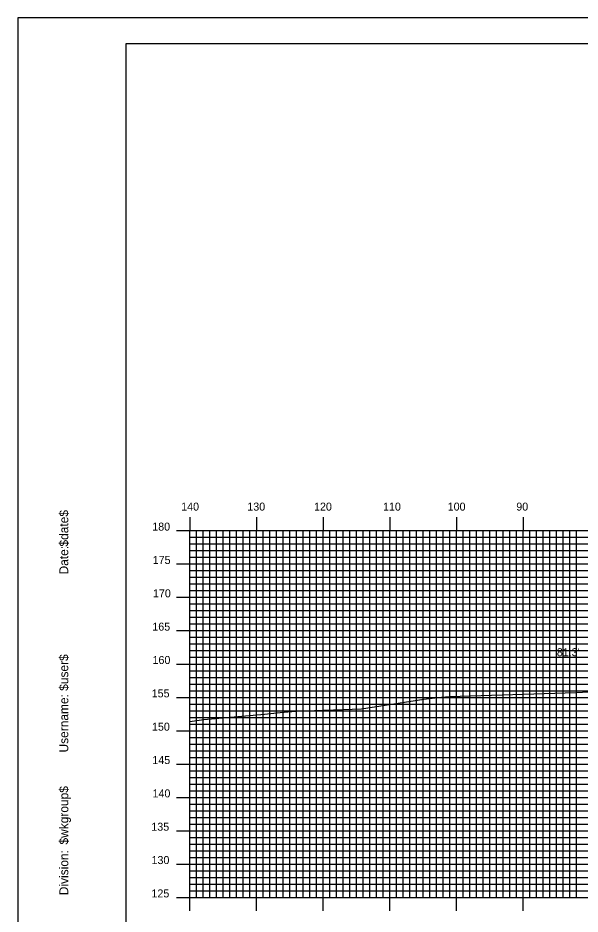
# Model space of a CAD drawing. Extents: x 1783434 to 1783777, y 442591 to 442811.
# Drawn here: x 1783434.2 to 1783518.5, y 442676.2 to 442810.5 of the extents above; entities that cross this region are included whole.
import ezdxf

# ---------------------------------------------------------------- set-up
doc = ezdxf.new("R2010")
doc.units = 0
for name, color, linetype in [('BORDER', 7, 'Continuous'), ('D_Text_Standard', 7, 'Continuous'), ('H_V ANNOTATION', 7, 'Continuous'), ('MAJOR', 7, 'Continuous'), ('MINOR', 7, 'Continuous'), ('PLOT BOUNDARY', 7, 'Continuous'), ('S_Roadway_Centerline', 7, 'Continuous')]:
    doc.layers.add(name, color=color, linetype=linetype)

msp = doc.modelspace()

# ---------------------------------------------------------------- linework, layer by layer
at = {"layer": 'BORDER'}
msp.add_lwpolyline([(1783450.37, 442596.67), (1783770.37, 442596.67), (1783770.37, 442806.67), (1783450.37, 442806.67)], close=True, dxfattribs=at)
at = {"layer": 'MAJOR'}
for p, q in [((1783459.97, 442735.67), (1783459.97, 442733.67)), ((1783469.97, 442735.67), (1783469.97, 442733.67)), ((1783479.97, 442735.67), (1783479.97, 442733.67)), ((1783489.97, 442735.67), (1783489.97, 442733.67)), ((1783499.97, 442735.67), (1783499.97, 442733.67)), ((1783509.97, 442735.67), (1783509.97, 442733.67)), ((1783457.97, 442733.67), (1783459.97, 442733.67)), ((1783459.97, 442733.67), (1783739.97, 442733.67)), ((1783459.97, 442678.67), (1783459.97, 442733.67)), ((1783459.97, 442678.67), (1783459.97, 442733.67)), ((1783459.97, 442733.67), (1783739.97, 442733.67)), ((1783469.97, 442678.67), (1783469.97, 442733.67)), ((1783479.97, 442678.67), (1783479.97, 442733.67)), ((1783489.97, 442678.67), (1783489.97, 442733.67)), ((1783499.97, 442678.67), (1783499.97, 442733.67)), ((1783509.97, 442678.67), (1783509.97, 442733.67)), ((1783457.97, 442728.67), (1783459.97, 442728.67)), ((1783459.97, 442728.67), (1783739.97, 442728.67)), ((1783457.97, 442723.67), (1783459.97, 442723.67)), ((1783459.97, 442723.67), (1783739.97, 442723.67)), ((1783457.97, 442718.67), (1783459.97, 442718.67)), ((1783459.97, 442718.67), (1783739.97, 442718.67)), ((1783457.97, 442713.67), (1783459.97, 442713.67)), ((1783459.97, 442713.67), (1783739.97, 442713.67)), ((1783457.97, 442708.67), (1783459.97, 442708.67)), ((1783459.97, 442708.67), (1783739.97, 442708.67)), ((1783457.97, 442703.67), (1783459.97, 442703.67)), ((1783459.97, 442703.67), (1783739.97, 442703.67)), ((1783457.97, 442698.67), (1783459.97, 442698.67)), ((1783459.97, 442698.67), (1783739.97, 442698.67)), ((1783457.97, 442693.67), (1783459.97, 442693.67)), ((1783459.97, 442693.67), (1783739.97, 442693.67)), ((1783457.97, 442688.67), (1783459.97, 442688.67)), ((1783459.97, 442688.67), (1783739.97, 442688.67)), ((1783457.97, 442683.67), (1783459.97, 442683.67)), ((1783459.97, 442683.67), (1783739.97, 442683.67)), ((1783457.97, 442678.67), (1783459.97, 442678.67)), ((1783459.97, 442678.67), (1783739.97, 442678.67)), ((1783459.97, 442678.67), (1783739.97, 442678.67)), ((1783459.97, 442676.66), (1783459.97, 442678.67)), ((1783469.97, 442676.66), (1783469.97, 442678.67)), ((1783479.97, 442676.66), (1783479.97, 442678.67)), ((1783489.97, 442676.66), (1783489.97, 442678.67)), ((1783499.97, 442676.66), (1783499.97, 442678.67)), ((1783509.97, 442676.66), (1783509.97, 442678.67))]:
    msp.add_line(p, q, dxfattribs=at)
at = {"layer": 'MINOR'}
for p, q in [((1783459.97, 442732.67), (1783739.97, 442732.67)), ((1783459.97, 442732.67), (1783461.98, 442732.67)), ((1783460.97, 442678.67), (1783460.97, 442733.67)), ((1783461.97, 442678.67), (1783461.97, 442733.67)), ((1783462.97, 442678.67), (1783462.97, 442733.67)), ((1783463.97, 442678.67), (1783463.97, 442733.67)), ((1783464.97, 442678.67), (1783464.97, 442733.67)), ((1783465.97, 442678.67), (1783465.97, 442733.67)), ((1783466.97, 442678.67), (1783466.97, 442733.67)), ((1783467.97, 442678.67), (1783467.97, 442733.67)), ((1783468.97, 442678.67), (1783468.97, 442733.67)), ((1783470.97, 442678.67), (1783470.97, 442733.67)), ((1783471.97, 442678.67), (1783471.97, 442733.67)), ((1783472.97, 442678.67), (1783472.97, 442733.67)), ((1783473.97, 442678.67), (1783473.97, 442733.67)), ((1783474.97, 442678.67), (1783474.97, 442733.67)), ((1783475.97, 442678.67), (1783475.97, 442733.67)), ((1783476.97, 442678.67), (1783476.97, 442733.67)), ((1783477.97, 442678.67), (1783477.97, 442733.67)), ((1783478.97, 442678.67), (1783478.97, 442733.67)), ((1783480.97, 442678.67), (1783480.97, 442733.67)), ((1783481.97, 442678.67), (1783481.97, 442733.67)), ((1783482.97, 442678.67), (1783482.97, 442733.67)), ((1783483.97, 442678.67), (1783483.97, 442733.67)), ((1783484.97, 442678.67), (1783484.97, 442733.67)), ((1783485.97, 442678.67), (1783485.97, 442733.67)), ((1783486.97, 442678.67), (1783486.97, 442733.67)), ((1783487.97, 442678.67), (1783487.97, 442733.67)), ((1783488.97, 442678.67), (1783488.97, 442733.67)), ((1783490.97, 442678.67), (1783490.97, 442733.67)), ((1783491.97, 442678.67), (1783491.97, 442733.67)), ((1783492.97, 442678.67), (1783492.97, 442733.67)), ((1783493.97, 442678.67), (1783493.97, 442733.67)), ((1783494.97, 442678.67), (1783494.97, 442733.67)), ((1783495.97, 442678.67), (1783495.97, 442733.67)), ((1783496.97, 442678.67), (1783496.97, 442733.67)), ((1783497.97, 442678.67), (1783497.97, 442733.67)), ((1783498.97, 442678.67), (1783498.97, 442733.67)), ((1783500.97, 442678.67), (1783500.97, 442733.67)), ((1783501.97, 442678.67), (1783501.97, 442733.67)), ((1783502.97, 442678.67), (1783502.97, 442733.67)), ((1783503.97, 442678.67), (1783503.97, 442733.67)), ((1783504.97, 442678.67), (1783504.97, 442733.67)), ((1783505.97, 442678.67), (1783505.97, 442733.67)), ((1783506.97, 442678.67), (1783506.97, 442733.67)), ((1783507.97, 442678.67), (1783507.97, 442733.67)), ((1783508.97, 442678.67), (1783508.97, 442733.67)), ((1783510.97, 442678.67), (1783510.97, 442733.67)), ((1783511.97, 442678.67), (1783511.97, 442733.67)), ((1783512.97, 442678.67), (1783512.97, 442733.67)), ((1783513.97, 442678.67), (1783513.97, 442733.67)), ((1783514.97, 442678.67), (1783514.97, 442733.67)), ((1783515.97, 442678.67), (1783515.97, 442733.67)), ((1783516.97, 442678.67), (1783516.97, 442733.67)), ((1783517.97, 442678.67), (1783517.97, 442733.67)), ((1783459.97, 442731.67), (1783739.97, 442731.67)), ((1783459.97, 442731.67), (1783461.98, 442731.67)), ((1783459.97, 442730.67), (1783739.97, 442730.67)), ((1783459.97, 442730.67), (1783461.98, 442730.67)), ((1783459.97, 442729.67), (1783739.97, 442729.67)), ((1783459.97, 442729.67), (1783461.98, 442729.67)), ((1783459.97, 442727.67), (1783739.97, 442727.67)), ((1783459.97, 442727.67), (1783461.98, 442727.67)), ((1783459.97, 442726.67), (1783739.97, 442726.67)), ((1783459.97, 442726.67), (1783461.98, 442726.67)), ((1783459.97, 442725.67), (1783739.97, 442725.67)), ((1783459.97, 442725.67), (1783461.98, 442725.67)), ((1783459.97, 442724.67), (1783739.97, 442724.67)), ((1783459.97, 442724.67), (1783461.98, 442724.67)), ((1783459.97, 442722.67), (1783739.97, 442722.67)), ((1783459.97, 442722.67), (1783461.98, 442722.67)), ((1783459.97, 442721.67), (1783739.97, 442721.67)), ((1783459.97, 442721.67), (1783461.98, 442721.67)), ((1783459.97, 442720.67), (1783739.97, 442720.67)), ((1783459.97, 442720.67), (1783461.98, 442720.67)), ((1783459.97, 442719.67), (1783739.97, 442719.67)), ((1783459.97, 442719.67), (1783461.98, 442719.67)), ((1783459.97, 442717.67), (1783739.97, 442717.67)), ((1783459.97, 442717.67), (1783461.98, 442717.67)), ((1783459.97, 442716.67), (1783739.97, 442716.67)), ((1783459.97, 442716.67), (1783461.98, 442716.67)), ((1783459.97, 442715.67), (1783739.97, 442715.67)), ((1783459.97, 442715.67), (1783461.98, 442715.67)), ((1783459.97, 442714.67), (1783739.97, 442714.67)), ((1783459.97, 442714.67), (1783461.98, 442714.67)), ((1783459.97, 442712.67), (1783739.97, 442712.67)), ((1783459.97, 442712.67), (1783461.98, 442712.67)), ((1783459.97, 442711.67), (1783739.97, 442711.67)), ((1783459.97, 442711.67), (1783461.98, 442711.67)), ((1783459.97, 442710.67), (1783739.97, 442710.67)), ((1783459.97, 442710.67), (1783461.98, 442710.67)), ((1783459.97, 442709.67), (1783739.97, 442709.67)), ((1783459.97, 442709.67), (1783461.98, 442709.67)), ((1783459.97, 442707.67), (1783739.97, 442707.67)), ((1783459.97, 442707.67), (1783461.98, 442707.67)), ((1783459.97, 442706.67), (1783739.97, 442706.67)), ((1783459.97, 442706.67), (1783461.98, 442706.67)), ((1783459.97, 442705.67), (1783739.97, 442705.67)), ((1783459.97, 442705.67), (1783461.98, 442705.67)), ((1783459.97, 442704.67), (1783739.97, 442704.67)), ((1783459.97, 442704.67), (1783461.98, 442704.67)), ((1783459.97, 442702.67), (1783739.97, 442702.67)), ((1783459.97, 442702.67), (1783461.98, 442702.67)), ((1783459.97, 442701.67), (1783739.97, 442701.67)), ((1783459.97, 442701.67), (1783461.98, 442701.67)), ((1783459.97, 442700.67), (1783739.97, 442700.67)), ((1783459.97, 442700.67), (1783461.98, 442700.67)), ((1783459.97, 442699.67), (1783739.97, 442699.67)), ((1783459.97, 442699.67), (1783461.98, 442699.67)), ((1783459.97, 442697.67), (1783739.97, 442697.67)), ((1783459.97, 442697.67), (1783461.98, 442697.67)), ((1783459.97, 442696.67), (1783739.97, 442696.67)), ((1783459.97, 442696.67), (1783461.98, 442696.67)), ((1783459.97, 442695.67), (1783739.97, 442695.67)), ((1783459.97, 442695.67), (1783461.98, 442695.67)), ((1783459.97, 442694.67), (1783739.97, 442694.67)), ((1783459.97, 442694.67), (1783461.98, 442694.67)), ((1783459.97, 442692.67), (1783739.97, 442692.67)), ((1783459.97, 442692.67), (1783461.98, 442692.67)), ((1783459.97, 442691.67), (1783739.97, 442691.67)), ((1783459.97, 442691.67), (1783461.98, 442691.67)), ((1783459.97, 442690.67), (1783739.97, 442690.67)), ((1783459.97, 442690.67), (1783461.98, 442690.67)), ((1783459.97, 442689.67), (1783739.97, 442689.67)), ((1783459.97, 442689.67), (1783461.98, 442689.67)), ((1783459.97, 442687.67), (1783739.97, 442687.67)), ((1783459.97, 442687.67), (1783461.98, 442687.67)), ((1783459.97, 442686.67), (1783739.97, 442686.67)), ((1783459.97, 442686.67), (1783461.98, 442686.67)), ((1783459.97, 442685.67), (1783739.97, 442685.67)), ((1783459.97, 442685.67), (1783461.98, 442685.67)), ((1783459.97, 442684.67), (1783739.97, 442684.67)), ((1783459.97, 442684.67), (1783461.98, 442684.67)), ((1783459.97, 442682.67), (1783739.97, 442682.67)), ((1783459.97, 442682.67), (1783461.98, 442682.67)), ((1783459.97, 442681.67), (1783739.97, 442681.67)), ((1783459.97, 442681.67), (1783461.98, 442681.67)), ((1783459.97, 442680.67), (1783739.97, 442680.67)), ((1783459.97, 442680.67), (1783461.98, 442680.67)), ((1783459.97, 442679.67), (1783739.97, 442679.67)), ((1783459.97, 442679.67), (1783461.98, 442679.67))]:
    msp.add_line(p, q, dxfattribs=at)
at = {"layer": 'PLOT BOUNDARY'}
msp.add_lwpolyline([(1783434.19, 442590.55), (1783774.19, 442590.55), (1783774.19, 442810.55), (1783434.19, 442810.55)], close=True, dxfattribs=at)
at = {"layer": 'S_Roadway_Centerline'}
msp.add_lwpolyline([(1783459.97, 442705.04), (1783462.07, 442705.34), (1783471.16, 442706.16), (1783473.55, 442706.4), (1783475.86, 442706.58), (1783485.71, 442706.96), (1783495.09, 442708.4), (1783497.12, 442708.63), (1783498.91, 442708.79), (1783517.9, 442709.42), (1783520.83, 442709.53)], dxfattribs=at)

# ---------------------------------------------------------------- texts
at = {"layer": 'BORDER'}
for s, p in [('$date$', (1783441.74, 442731.28)), ('$date$', (1783441.74, 442731.28)), ('Date:', (1783441.74, 442727.1)), ('Date:', (1783441.74, 442727.1)), ('$user$', (1783441.74, 442709.65)), ('$user$', (1783441.74, 442709.65)), ('Username:', (1783441.74, 442700.4)), ('Username:', (1783441.74, 442700.4)), ('$wkgroup$', (1783441.74, 442686.6)), ('$wkgroup$', (1783441.74, 442686.6)), ('Division:', (1783441.74, 442679)), ('Division:', (1783441.74, 442679))]:
    msp.add_text(s, height=1.339, rotation=90, dxfattribs=at).set_placement(p)
at = {"layer": 'D_Text_Standard'}
msp.add_text("81.3'", height=1.2, dxfattribs=at).set_placement((1783515.03, 442714.84))
at = {"layer": 'H_V ANNOTATION'}
for s, p in [('140', (1783458.68, 442736.67)), ('130', (1783468.6, 442736.67)), ('120', (1783478.61, 442736.67)), ('110', (1783488.96, 442736.67)), ('100', (1783498.66, 442736.67)), ('90', (1783508.95, 442736.67)), ('180', (1783454.34, 442733.67)), ('175', (1783454.41, 442728.67)), ('170', (1783454.45, 442723.67)), ('165', (1783454.35, 442718.67)), ('160', (1783454.38, 442713.67)), ('155', (1783454.26, 442708.67)), ('150', (1783454.3, 442703.67)), ('145', (1783454.35, 442698.67)), ('140', (1783454.38, 442693.67)), ('135', (1783454.2, 442688.67)), ('130', (1783454.23, 442683.67)), ('125', (1783454.22, 442678.67))]:
    msp.add_text(s, height=1.2, dxfattribs=at).set_placement(p)
at = {"layer": 'MAJOR'}
msp.add_text('-', height=0.012, dxfattribs=at).set_placement((1783459.96, 442678.67))

doc.saveas('drawing.dxf')
